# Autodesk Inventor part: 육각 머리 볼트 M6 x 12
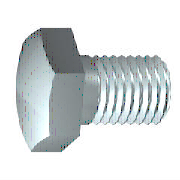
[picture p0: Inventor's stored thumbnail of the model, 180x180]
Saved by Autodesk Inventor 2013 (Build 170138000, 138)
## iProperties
IsCustomPart: 1
Created: 2012-02
Part Number: 육각 머리 볼트 M6 x 12
Material: 강철, 연강
Description: 6각 머리 나사
Document SubType Name: Modeling
Standard: ISO 4017
Designer: mdu-01
Standard Revision: Third edition 1999-08-15
Standards Organization: ISO
Language: ko-KR
Size Designation: M6 x 12
Categories: <MemberInstance><Categories><Category DisplayName="조임쇠" InternalName="e4da775c-781d-43d5-af7c-5136215cf5a6" Mnemonic="FSTN"><Category DisplayName="볼트" InternalN
Density: 7.75 g/cm^3
Author: mdu-01
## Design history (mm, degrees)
sketch "스케치1"
  geometry: L1 (0, 4.44)-(0, 3); L2 (3, 3)-(12, 3); L3 (12, 3)-(12, 0); L4 (12, 0)-(-0.5, 0); L5 (-3, 0)-(14.5, 0) reference; L6 (-0.5, 0)-(-0.5, 4.44); L7 (-0.5, 4.44)-(0, 4.44); L8 (3, 3)-(2.386, 3); L9 (2.386, 3)-(0, 3); L10 (0, -0.888)-(0, 5.328) reference
  constraints: 16 end point, 2 collinear, 2 perpendicular, 1 parallel
  dimensions: "d0" = 12 distance between parallel lines of L3 L1 (= NLG); "d1" = 9 distance from line of L2.start L3 (= GEL); "d2" = 6 diameter of L2 L4 (= GD); "d9" = 0.5001 distance between parallel lines of L6 L1 (computed from SD); "d10" = 8.88 diameter of L7 L4 (= SD2); "d13" = 0.61355 distance of L2.start L8.end (computed from GAL); "d14" = 6 diameter of L9 L4 (= BDM)
revolve "본체" sketch "스케치1" stored, may be unused: angle "d12" = 90 deg
sketch "스케치2"
  geometry: L1 (0, 5.774)-(5, 2.887); L2 (5, 2.887)-(5, -2.887); L3 (5, -2.887)-(0, -5.774); L4 (0, -5.774)-(-5, -2.887); L5 (-5, -2.887)-(-5, 2.887); L6 (-5, 2.887)-(0, 5.774); 2 further points
  constraints: 12 end point, 1 coincident, 1 vertical, 11 other
  dimensions: "d11" = 10 distance between parallel lines of L5 L2 (= SW)
extrude "머리" join sketch "스케치2" distance "d3" = 3.5 (= KOH - SD); taper "d4" = 0 deg
sketch "스케치4"
  geometry: L1 (-4, 5)-(-4, 5.774); L2 (-4, 5.774)-(-3.554, 5.774); L3 (-3.554, 5.774)-(-4, 5); L4 (-4.7, 0)-(0.2, 0) reference; L5 (-0.5, 5.774)-(-4, 5.774) reference; L6 (-4, 2.887)-(-4, 5.774) reference
  constraints: 6 end point, 2 collinear, 1 perpendicular, 1 vertical
  dimensions: "d5" = 30 deg angle of L3 L1 (= ANG1); "d19" = 10 diameter of L1.start L4 (= SW0)
revolve "모따기1" sketch "스케치4" stored, may be unused: angle "d21" = 90 deg
workplane "Work Plane1"
body "Solid1"
feature "스레드" dims "d15" = 9 (= GEL), "d16" = 0
chamfer "모따기2" distance "d6" = 0.61345 (= -0.5 x SPD + 0.5 x GD); stored, may be unused: second distance "d7" = 0.61355 (computed from GUL), angle "d55" = 45 deg
other parameters: "NLG" = 12 [user parameter; used in 1 equation term], "GD" = 6 (= NND) [user parameter; used in 2 equation terms], "BDM" = 6 (= NND) [user parameter; used in 1 equation term], "KOH" = 4 [user parameter; used in 1 equation term], "GEL" = 9 [user parameter; used in 2 equation terms], "SW" = 10 [user parameter; used in 2 equation terms], "SW0" = 10 (= SW) [user parameter; used in 1 equation term], "SPD" = 4.7731 (= NND - 1.2269 x PTC) [user parameter; used in 1 equation term], "SD2" = 8.88 [user parameter; used in 2 equation terms], "SD" = 0.5 [user parameter; used in 2 equation terms], "ANG1" = 30 deg [user parameter; used in 1 equation term], "GAL" = 0.61345 (= 0.61345 x PTC) [user parameter; used in 1 equation term], "GUL" = 0.61345 (= 0.61345 x PTC) [user parameter; used in 1 equation term], "d8" = 0, "RR" = 0.25 [user parameter], "d57" = 0, "d58" = 0, "GD1" = 4.7731 (= THREADDIA - 1.2269 x PTC) [user parameter], "THREADDIA" = 6 [user parameter; used in 1 equation term], "SDH" = 8.88 (= SD2) [user parameter], "SDHG" = 3 [user parameter], "TOA" = 30 deg [user parameter], "PTC" = 1 [user parameter; used in 5 equation terms], "NND" = 6 [user parameter; used in 3 equation terms], "E0" = 11.55 [user parameter]
